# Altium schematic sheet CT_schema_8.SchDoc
size 277 x 170 mm
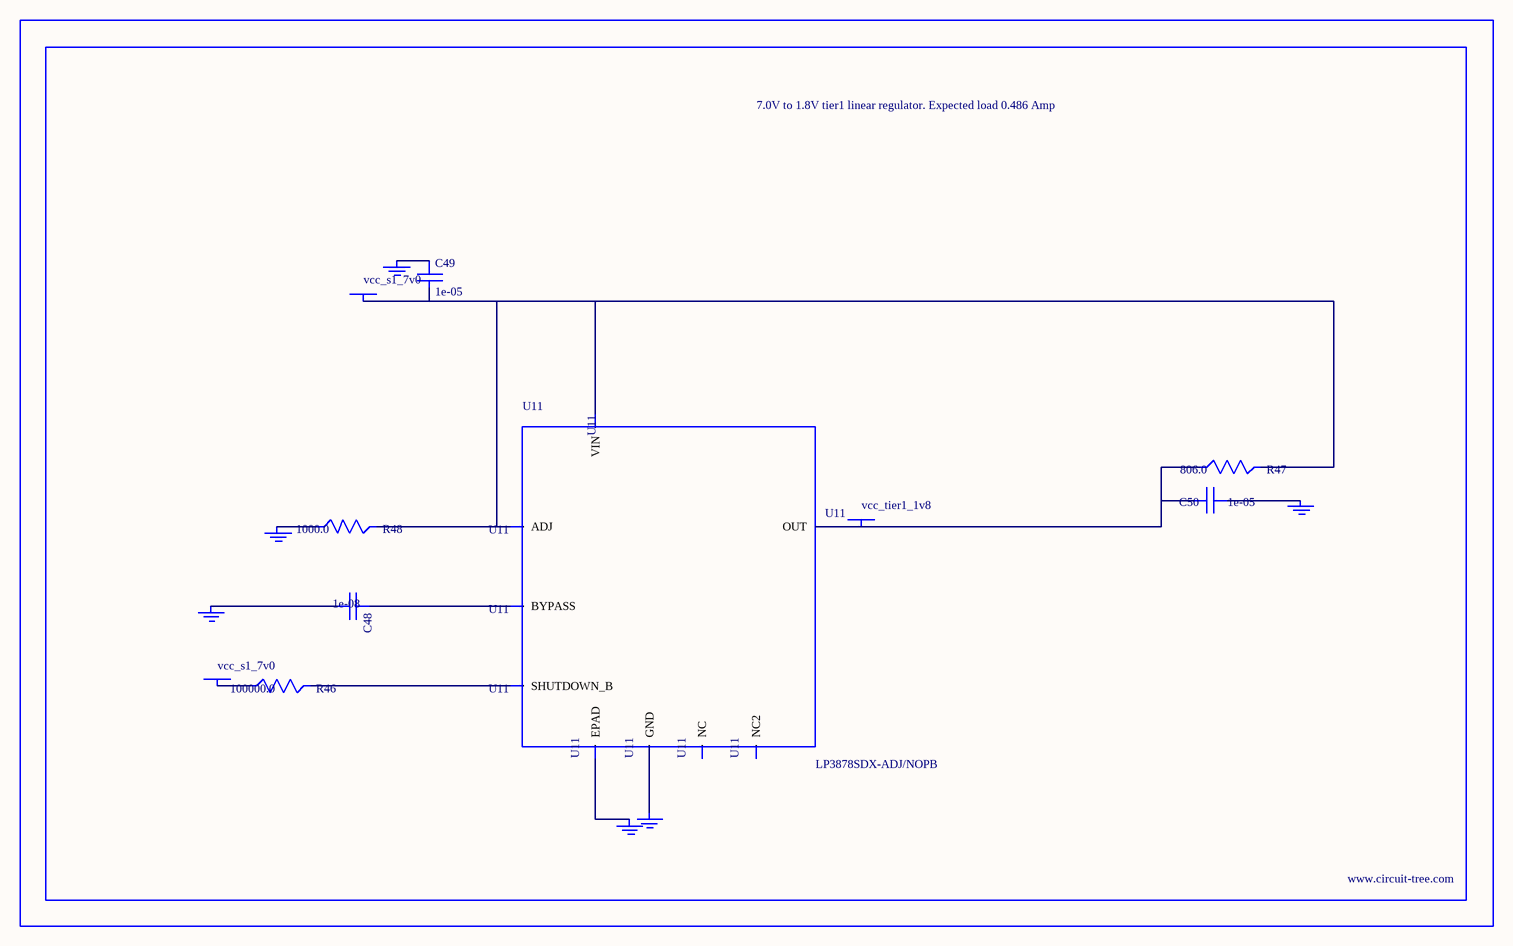
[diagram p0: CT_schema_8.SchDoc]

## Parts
BORDER7  (no value)
C48  1e-08  [C0402]
C49  1e-05  [C1206]
C50  1e-05  [C0805]
GND_INSTANCE_7_0  (no value)
GND_INSTANCE_7_1  (no value)
GND_INSTANCE_7_2  (no value)
GND_INSTANCE_7_3  (no value)
GND_INSTANCE_7_4  (no value)
GND_INSTANCE_7_5  (no value)
POWER_INSTANCE_7_0  vcc_s1_7v0
POWER_INSTANCE_7_1  vcc_s1_7v0
POWER_INSTANCE_7_2  vcc_tier1_1v8
R46  100000.0  [R0603]
R47  806.0  [R0603]
R48  1000.0  [R0603]
U11  LP3878SDX-ADJ/NOPB  [WSON-8]

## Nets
NetC48_1: C48.1 U11.1(BYPASS)
NetC48_2: C48.2 GND_INSTANCE_7_0.0(GND)
NetC49_1: C49.1 GND_INSTANCE_7_1.0(GND)
NetC49_2: C49.2 POWER_INSTANCE_7_0.0(PWR) R47.2 R48.2 U11.4(VIN) U11.6(ADJ)
NetC50_1: C50.1 GND_INSTANCE_7_2.0(GND)
NetC50_2: C50.2 POWER_INSTANCE_7_2.0(PWR) R47.1 U11.5(OUT)
NetGND_INSTANCE_7_3_0: GND_INSTANCE_7_3.0(GND) R48.1
NetGND_INSTANCE_7_4_0: GND_INSTANCE_7_4.0(GND) U11.PAD(EPAD)
NetGND_INSTANCE_7_5_0: GND_INSTANCE_7_5.0(GND) U11.3(GND)
NetPOWER_INSTANCE_7_1_0: POWER_INSTANCE_7_1.0(PWR) R46.1
NetR46_2: R46.2 U11.8(SHUTDOWN_B)

Not connected (* = marked no-connect by the designer): U11 2(NC) 7(NC2)

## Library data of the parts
BORDER7 = BORDER_PAGE7
C48 = C0402C103K3RAC
C49 = C1206C106K3RACTU
C50 = GRM219R60J106ME19D
GND_INSTANCE_7_0-GND_INSTANCE_7_5 = GND
POWER_INSTANCE_7_0-POWER_INSTANCE_7_2 = PWR
R46 = RC0603JR-07100KL
R47 = ERJ-3EKF8060V
R48 = RC0603JR-071KL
